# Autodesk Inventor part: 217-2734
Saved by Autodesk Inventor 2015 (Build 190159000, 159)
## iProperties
Created: 2014-11
Part Number: 217-2734
Material: Generic
Document SubType Name: Modeling
Designer: User
Density: 1 g/cm^3
Appearance: Default
Author: User
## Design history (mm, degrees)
node "217-2734.ipt1"
node "Cut-Extrude1"
node "Base1"
